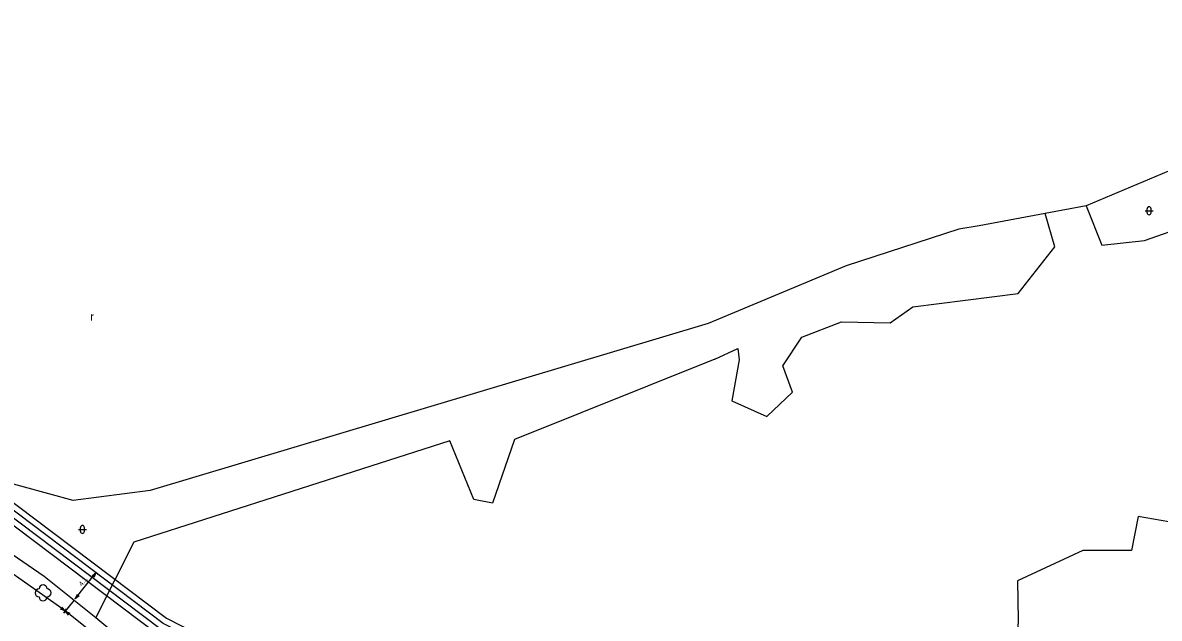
# Model space of a CAD drawing. Extents: x -836739 to -834468, y -1071001 to -1070126.
# Drawn here: x -836580.6 to -836438.6, y -1070200.2 to -1070125.8 of the extents above; entities that cross this region are included whole.
import ezdxf

# ---------------------------------------------------------------- set-up
doc = ezdxf.new("R2010")
doc.units = 0
for name, color, linetype in [('f001_pol_linie', 7, 'Continuous'), ('f001_pol_znacky', 7, 'Continuous'), ('f006_osa_trasy', 7, 'Continuous'), ('f006_stp_koty', 7, 'Continuous'), ('f309_trubka', 7, 'Continuous')]:
    doc.layers.add(name, color=color, linetype=linetype)

msp = doc.modelspace()

# ---------------------------------------------------------------- linework, layer by layer
at = {"layer": 'f001_pol_linie'}
for points in [[(-836404.38, -1070205.23), (-836402.5, -1070201.83), (-836397.02, -1070198.53), (-836393.57, -1070195.71), (-836388.95, -1070189.69), (-836384.03, -1070176.12), (-836378.56, -1070158.89), (-836372.13, -1070144.62), (-836365.93, -1070132.95), (-836364.19, -1070126.7), (-836369.77, -1070125.77), (-836373.7, -1070126.07), (-836388.8, -1070131.24), (-836403.54, -1070136.21), (-836415.72, -1070138.17), (-836422.93, -1070140.33), (-836427.24, -1070141.62), (-836436.7, -1070143.96), (-836447.77, -1070148.66), (-836452.9, -1070149.61), (-836461.16, -1070151.13), (-836463.68, -1070151.54), (-836477.77, -1070156.14), (-836494.99, -1070163.36)], [(-836447.77, -1070148.66), (-836445.81, -1070153.54), (-836440.48, -1070152.98), (-836435.02, -1070151.06), (-836423.96, -1070146.4), (-836422.06, -1070144.37), (-836422.93, -1070140.33)], [(-836494.17, -1070167.78), (-836491.31, -1070166.45), (-836491.14, -1070167.9), (-836492.05, -1070172.99), (-836487.66, -1070174.97), (-836484.46, -1070171.93), (-836485.69, -1070168.61), (-836483.32, -1070165.03), (-836478.36, -1070163.13), (-836472.25, -1070163.25), (-836469.44, -1070161.28), (-836456.29, -1070159.61), (-836451.7, -1070153.75), (-836452.9, -1070149.61)], [(-836494.99, -1070163.36), (-836564.73, -1070184.21)], [(-836646.79, -1070164.47), (-836635.17, -1070166.04), (-836623.33, -1070167.88), (-836615.58, -1070169.1), (-836607.83, -1070173.77), (-836593.75, -1070183.78), (-836585.2, -1070189.95), (-836577.96, -1070194.89), (-836571.5, -1070200.08), (-836562.11, -1070207.9), (-836555.43, -1070213.46), (-836552.63, -1070222.02), (-836550.05, -1070228.71)], [(-836564.73, -1070184.21), (-836574.34, -1070185.45), (-836586.56, -1070182.14), (-836613.97, -1070167.29)], [(-836494.17, -1070167.78), (-836519.2, -1070177.84), (-836521.97, -1070185.78), (-836524.29, -1070185.33), (-836527.29, -1070177.98), (-836566.77, -1070190.66), (-836571.5, -1070200.08)], [(-836407.94, -1070215.36), (-836407.56, -1070210.18), (-836413.05, -1070209.34), (-836414.73, -1070212.35), (-836416.59, -1070212.35), (-836417.38, -1070208.23), (-836421.71, -1070206.15), (-836429.78, -1070207.83), (-836431.61, -1070207.55), (-836429.74, -1070199.16), (-836429.36, -1070196.51), (-836430.24, -1070193.56), (-836432.87, -1070193.97), (-836435.74, -1070192.18), (-836435.55, -1070188.45), (-836441.3, -1070187.44), (-836442.12, -1070191.71), (-836448.21, -1070191.72), (-836456.38, -1070195.47), (-836456.29, -1070200.41), (-836456.56, -1070206.45), (-836454.52, -1070211.62), (-836451, -1070214.46), (-836443.91, -1070214.91)]]:
    msp.add_lwpolyline(points, dxfattribs=at)
at = {"layer": 'f001_pol_znacky'}
for p, q in [((-836440.42, -1070149.26), (-836439.42, -1070149.26)), ((-836440.17, -1070149.51), (-836440.17, -1070149.01)), ((-836439.67, -1070149.51), (-836439.67, -1070149.01)), ((-836573.68, -1070189.07), (-836572.68, -1070189.07)), ((-836573.43, -1070189.32), (-836573.43, -1070188.82)), ((-836572.93, -1070189.32), (-836572.93, -1070188.82))]:
    msp.add_line(p, q, dxfattribs=at)
msp.add_circle((-836578.1, -1070196.99), 0.0005, dxfattribs=at)
for centre, radius, start, end in [((-836439.92, -1070149.01), 0.25, 0, 180), ((-836439.92, -1070149.51), 0.25, 180, 360), ((-836573.18, -1070188.82), 0.25, 0, 180), ((-836573.18, -1070189.32), 0.25, 180, 360), ((-836578.6, -1070196.99), 0.5, 90, 270), ((-836578.1, -1070196.49), 0.5, 0, 180), ((-836577.6, -1070196.99), 0.5, 270, 90), ((-836578.1, -1070197.49), 0.5, 180, 360)]:
    msp.add_arc(centre, radius, start, end, dxfattribs=at)
at = {"layer": 'f006_osa_trasy'}
msp.add_lwpolyline([(-836471.29, -1070247.06), (-836475.13, -1070240.07), (-836481.69, -1070223.19), (-836484.06, -1070219.25), (-836486.31, -1070218.35), (-836503.86, -1070214.94), (-836526.3, -1070212.27), (-836553.58, -1070205.67), (-836563.09, -1070200.8), (-836595.87, -1070176.09), (-836614.86, -1070165.34), (-836629.43, -1070164.09), (-836642.16, -1070162.86), (-836653.58, -1070160.22), (-836662.77, -1070161.03), (-836672.46, -1070165.03), (-836697.35, -1070176), (-836703.68, -1070184.13), (-836710.27, -1070188.76)], dxfattribs=at)
at = {"layer": 'f006_stp_koty'}
for points in [[(-836575.34, -1070199.24), (-836599.96, -1070181.91)], [(-836574.08, -1070197.73), (-836571.5, -1070194.5)], [(-836571.99, -1070194.87), (-836571.5, -1070194.5), (-836571.76, -1070195.06)], [(-836571.32, -1070194.64), (-836571.27, -1070194.68)], [(-836574.27, -1070197.96), (-836575.49, -1070199.5)], [(-836573.59, -1070197.35), (-836574.08, -1070197.73), (-836573.82, -1070197.17)], [(-836575.74, -1070198.77), (-836575.34, -1070199.24), (-836575.91, -1070199.02)], [(-836575.53, -1070199.52), (-836575.16, -1070199)], [(-836567.09, -1070205.82), (-836575.31, -1070199.27)], [(-836574.93, -1070199.76), (-836575.31, -1070199.27), (-836574.74, -1070199.52)]]:
    msp.add_lwpolyline(points, dxfattribs=at)
at = {"layer": 'f309_trubka'}
for points in [[(-836710.7, -1070188.15), (-836710.09, -1070187.72), (-836704.2, -1070183.58), (-836697.83, -1070175.39), (-836672.75, -1070164.34), (-836662.95, -1070160.29), (-836653.53, -1070159.46), (-836642.04, -1070162.12), (-836629.36, -1070163.34), (-836614.63, -1070164.61), (-836595.46, -1070175.46), (-836562.69, -1070200.16), (-836553.32, -1070204.96), (-836526.17, -1070211.53), (-836503.74, -1070214.2), (-836486.1, -1070217.63), (-836483.55, -1070218.65), (-836481.01, -1070222.86), (-836474.45, -1070239.75), (-836470.63, -1070246.7)], [(-836471.29, -1070247.06), (-836475.13, -1070240.07), (-836481.69, -1070223.19), (-836484.06, -1070219.25), (-836486.31, -1070218.35), (-836503.86, -1070214.94), (-836526.3, -1070212.27), (-836553.58, -1070205.67), (-836563.09, -1070200.8), (-836595.87, -1070176.09), (-836614.86, -1070165.34), (-836629.43, -1070164.09), (-836642.16, -1070162.86), (-836653.58, -1070160.22), (-836662.77, -1070161.03), (-836672.46, -1070165.03), (-836697.35, -1070176), (-836703.68, -1070184.13), (-836709.66, -1070188.33), (-836710.27, -1070188.76)], [(-836709.84, -1070189.37), (-836709.22, -1070188.94), (-836703.16, -1070184.68), (-836696.87, -1070176.61), (-836672.17, -1070165.72), (-836662.59, -1070161.77), (-836653.63, -1070160.98), (-836642.28, -1070163.6), (-836629.5, -1070164.84), (-836615.09, -1070166.07), (-836596.28, -1070176.72), (-836563.49, -1070201.44), (-836553.84, -1070206.38), (-836526.43, -1070213.01), (-836503.98, -1070215.68), (-836486.52, -1070219.07), (-836484.57, -1070219.85), (-836482.37, -1070223.52), (-836475.81, -1070240.39), (-836471.95, -1070247.42)], [(-836709.41, -1070189.99), (-836708.79, -1070189.56), (-836702.63, -1070185.23), (-836696.4, -1070177.22), (-836671.87, -1070166.41), (-836662.41, -1070162.5), (-836653.69, -1070161.74), (-836642.4, -1070164.34), (-836629.57, -1070165.58), (-836615.31, -1070166.81), (-836596.69, -1070177.35), (-836563.89, -1070202.08), (-836554.11, -1070207.09), (-836526.57, -1070213.75), (-836504.09, -1070216.42), (-836486.74, -1070219.8), (-836485.09, -1070220.46), (-836483.04, -1070223.85), (-836476.49, -1070240.71), (-836472.61, -1070247.78)]]:
    msp.add_lwpolyline(points, dxfattribs=at)

# ---------------------------------------------------------------- texts
at = {"layer": 'f001_pol_znacky'}
msp.add_text('r', height=1, dxfattribs=at).set_placement((-836572.21, -1070162.98))
at = {"layer": 'f006_stp_koty'}
msp.add_text('4.1', height=0.6, rotation=51.44, dxfattribs=at).set_placement((-836573.25, -1070196.21))

doc.saveas('drawing.dxf')
